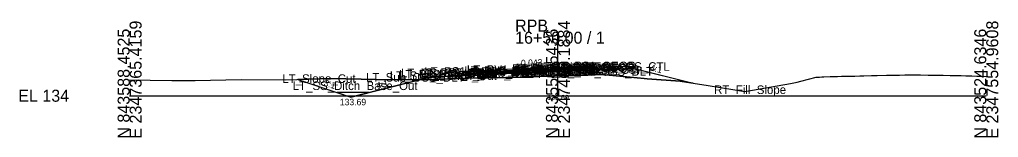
# Model space of a CAD drawing. Extents: x -76 to 2347760, y -10 to 844216.
# Drawn here: x -25.7 to 202.8, y 1490.3 to 1517.7 of the extents above; entities that cross this region are included whole.
import ezdxf

# ---------------------------------------------------------------- set-up
doc = ezdxf.new("R2010")
doc.units = 0
for name, color, linetype in [('Default', 7, 'Continuous'), ('Exist Cross Section Cell', 7, 'Continuous'), ('Exist XS Center Line Elevation Label', 7, 'Continuous'), ('Exist XS Ground Line', 7, 'Continuous'), ('Prop CMT Pvmt Course 1', 7, 'Continuous'), ('Prop CMT Pvmt Course 2', 7, 'Continuous'), ('Prop CMT Pvmt Course 3', 7, 'Continuous'), ('Prop CMT Pvmt Surface', 7, 'Continuous'), ('Prop CMT Pvmt Surface Shoulder', 7, 'Continuous'), ('Prop CMT Shld Paved Course 1', 7, 'Continuous'), ('Prop CMT Shld Paved Course 2', 7, 'Continuous'), ('Prop CMT Shld Paved Course 3', 7, 'Continuous'), ('Prop CMT Slope Grass', 7, 'Continuous'), ('Prop CMT Subgrade Earthwork', 7, 'Continuous'), ('Prop Road Sect_ Recs - UUC (Outline)', 7, 'Continuous'), ('Prop XS Ditch Standard Text', 7, 'Continuous'), ('Prop XS Earthwork Shape', 7, 'Continuous'), ('Prop XS SE Text', 7, 'Continuous'), ('Prop XS Side Slope Text', 7, 'Continuous'), ('Scratch_Level_0', 7, 'Continuous')]:
    doc.layers.add(name, color=color, linetype=linetype)

msp = doc.modelspace()

# ---------------------------------------------------------------- linework, layer by layer
at = {"layer": 'Exist Cross Section Cell'}
for p, q in [((100, 1500), (100, 1514.91)), ((0, 1500), (100, 1500)), ((100, 1500), (200, 1500))]:
    msp.add_line(p, q, dxfattribs=at)
at = {"layer": 'Exist XS Ground Line'}
msp.add_lwpolyline([(0, 1503.69), (4.77, 1503.59), (9.86, 1503.56), (15.32, 1503.51), (26.08, 1503.74), (36.43, 1503.71), (41.68, 1503.88), (46.98, 1504.01), (57.59, 1503.81), (68.08, 1503.69), (73.49, 1503.88), (78.63, 1504.12), (88.76, 1504.26), (89.4, 1504.28), (100, 1504.6), (105.31, 1504.73), (110.29, 1504.97), (120.1, 1503.98), (120.84, 1503.9), (128.55, 1503.38), (135.08, 1502.36), (140.86, 1501.43), (143.65, 1500.98), (154.26, 1502.88), (155.87, 1503.17), (156.69, 1503.39), (160.29, 1504.3), (161.06, 1504.31), (161.61, 1504.38), (162.08, 1504.4), (163.53, 1504.44), (165.29, 1504.49), (166.19, 1504.52), (167.97, 1504.57), (168.81, 1504.58), (169.33, 1504.59), (170.48, 1504.61), (171.38, 1504.64), (173.23, 1504.68), (174.08, 1504.7), (174.52, 1504.71), (176.73, 1504.76), (178.54, 1504.8), (179.35, 1504.81), (179.75, 1504.82), (180.99, 1504.85), (182.04, 1504.87), (182.6, 1504.87), (183.24, 1504.86), (184.61, 1504.85), (186.46, 1504.82), (187.25, 1504.81), (187.64, 1504.81), (188.86, 1504.79), (189.91, 1504.77), (191.59, 1504.73), (192.53, 1504.71), (194.17, 1504.68), (195.24, 1504.66), (196.65, 1504.6), (197.81, 1504.57), (198.42, 1504.54), (200, 1504.49)], dxfattribs=at)
at = {"layer": 'Prop CMT Pvmt Course 1'}
for p, q in [((100, 1506.59), (88, 1506.07)), ((88, 1505.82), (100, 1506.34)), ((88, 1506.07), (88, 1505.82)), ((100, 1506.59), (104, 1506.76)), ((100, 1506.34), (100, 1506.59)), ((100, 1506.34), (100, 1506.59)), ((104, 1506.51), (100, 1506.34)), ((100, 1506.34), (100, 1506.46)), ((100, 1506.46), (100, 1506.46)), ((100, 1506.46), (100, 1506.34)), ((100, 1506.34), (100, 1506.46)), ((100, 1506.46), (100, 1506.46)), ((100, 1506.46), (100, 1506.34)), ((100, 1506.34), (100, 1506.34)), ((100, 1506.34), (100, 1506.34)), ((104, 1506.76), (104, 1506.51))]:
    msp.add_line(p, q, dxfattribs=at)
at = {"layer": 'Prop CMT Pvmt Course 2'}
for p, q in [((100, 1506.34), (88, 1505.82)), ((100, 1506.34), (104, 1506.51)), ((100, 1506.01), (100, 1506.34)), ((100, 1506.01), (100, 1506.34)), ((104, 1506.18), (100, 1506.01)), ((104, 1506.51), (104, 1506.18)), ((88, 1505.49), (100, 1506.01)), ((88, 1505.82), (88, 1505.49))]:
    msp.add_line(p, q, dxfattribs=at)
at = {"layer": 'Prop CMT Pvmt Course 3'}
for p, q in [((100, 1506.01), (104, 1506.18)), ((104, 1506.18), (104, 1505.85)), ((100, 1506.01), (88, 1505.49)), ((88, 1505.15), (100, 1505.67)), ((88, 1505.49), (88, 1505.15)), ((100, 1505.67), (100, 1506.01)), ((100, 1505.67), (100, 1506.01)), ((104, 1505.85), (100, 1505.67))]:
    msp.add_line(p, q, dxfattribs=at)
at = {"layer": 'Prop CMT Pvmt Surface'}
for q in [(88, 1506.07), (104, 1506.76)]:
    msp.add_line((100, 1506.59), q, dxfattribs=at)
at = {"layer": 'Prop CMT Pvmt Surface Shoulder'}
for p, q in [((88, 1506.07), (78, 1505.64)), ((104, 1506.76), (108, 1506.94))]:
    msp.add_line(p, q, dxfattribs=at)
at = {"layer": 'Prop CMT Shld Paved Course 1'}
for p, q in [((88, 1506.07), (78, 1505.64)), ((88, 1505.82), (88, 1506.07)), ((104, 1506.76), (108, 1506.94)), ((104, 1506.51), (104, 1506.76)), ((108.24, 1506.7), (104, 1506.51)), ((108, 1506.94), (108.24, 1506.7)), ((77.74, 1505.38), (88, 1505.82)), ((78, 1505.64), (77.74, 1505.38))]:
    msp.add_line(p, q, dxfattribs=at)
at = {"layer": 'Prop CMT Shld Paved Course 2'}
for p, q in [((104, 1506.51), (108.24, 1506.7)), ((104, 1506.18), (104, 1506.51)), ((108.56, 1506.38), (104, 1506.18)), ((108.24, 1506.7), (108.56, 1506.38)), ((77.39, 1505.03), (88, 1505.49)), ((77.74, 1505.38), (77.39, 1505.03)), ((88, 1505.82), (77.74, 1505.38)), ((88, 1505.49), (88, 1505.82))]:
    msp.add_line(p, q, dxfattribs=at)
at = {"layer": 'Prop CMT Shld Paved Course 3'}
for p, q in [((104, 1506.18), (108.56, 1506.38)), ((104, 1505.85), (104, 1506.18)), ((109.38, 1506.08), (104, 1505.85)), ((108.56, 1506.38), (109.06, 1506.4)), ((109.06, 1506.4), (109.38, 1506.08)), ((76.54, 1504.66), (88, 1505.15)), ((76.89, 1505.01), (76.54, 1504.66)), ((77.39, 1505.03), (76.89, 1505.01)), ((88, 1505.49), (77.39, 1505.03)), ((88, 1505.15), (88, 1505.49))]:
    msp.add_line(p, q, dxfattribs=at)
at = {"layer": 'Prop CMT Slope Grass'}
for p, q in [((108, 1506.94), (116, 1506.8)), ((108, 1506.94), (116, 1506.8)), ((116, 1506.8), (131.6, 1502.9)), ((39.28, 1503.8), (51.63, 1499.69)), ((74.24, 1505.34), (51.63, 1499.69)), ((78, 1505.64), (74.24, 1505.34))]:
    msp.add_line(p, q, dxfattribs=at)
at = {"layer": 'Prop CMT Subgrade Earthwork'}
for p, q in [((104, 1505.85), (117.49, 1506.43)), ((76.54, 1504.66), (70.48, 1504.4)), ((88, 1505.15), (76.54, 1504.66)), ((100, 1505.67), (88, 1505.15)), ((100, 1505.67), (104, 1505.85))]:
    msp.add_line(p, q, dxfattribs=at)
at = {"layer": 'Prop Road Sect_ Recs - UUC (Outline)'}
msp.add_lwpolyline([(48.49, 1500.73), (51.63, 1499.69), (55.83, 1500.73)], close=True, dxfattribs=at)
at = {"layer": 'Prop XS Earthwork Shape'}
for points in [[(100, 1505.67), (104, 1505.85), (117.49, 1506.43), (131.6, 1502.9), (128.55, 1503.38), (120.84, 1503.9), (120.1, 1503.98), (110.29, 1504.97), (105.31, 1504.73), (100, 1504.6), (89.4, 1504.28), (88.76, 1504.26), (78.63, 1504.12), (73.49, 1503.88), (68.08, 1503.69), (67.68, 1503.7), (70.48, 1504.4), (76.54, 1504.66), (88, 1505.15)], [(39.28, 1503.8), (51.63, 1499.69), (67.68, 1503.7), (57.59, 1503.81), (46.98, 1504.01), (41.68, 1503.88)]]:
    msp.add_lwpolyline(points, close=True, dxfattribs=at)

# ---------------------------------------------------------------- texts
at = {"layer": 'Default'}
msp.add_text('-', height=0.0001, dxfattribs=at).set_placement((0, 1500))
at = {"layer": 'Exist Cross Section Cell'}
for s, p in [('RPB', (90, 1514.91)), ('16+50.00 / 1', (90, 1512.11)), ('EL 134', (-26, 1498.6))]:
    msp.add_text(s, height=2.8, dxfattribs=at).set_placement(p)
for s, p in [('N 843588.4525', (0, 1490)), ('E 2347365.4159', (2.8, 1490)), ('N 843556.5436', (100, 1490)), ('E 2347460.1884', (102.8, 1490)), ('N 843524.6346', (200, 1490)), ('E 2347554.9608', (202.8, 1490))]:
    msp.add_text(s, height=2.8, rotation=90, dxfattribs=at).set_placement(p)
at = {"layer": 'Exist XS Center Line Elevation Label'}
msp.add_text('138.60', height=1.2, dxfattribs=at).set_placement((97.48, 1499))
at = {"layer": 'Prop XS Ditch Standard Text'}
msp.add_text('133.69', height=1.5, dxfattribs=at).set_placement((49.08, 1497.78))
at = {"layer": 'Prop XS SE Text'}
msp.add_text('0.043', height=1.5, rotation=2.4746, dxfattribs=at).set_placement((91.4, 1506.84))
at = {"layer": 'Prop XS Side Slope Text'}
for s, rotation, p in [('4:1', 345.5351, (121.42, 1505.92)), ('3:1', 341.6601, (45.2, 1502.4)), ('4:1', 14.0362, (57.82, 1501.6))]:
    msp.add_text(s, height=1.5, rotation=rotation, dxfattribs=at).set_placement(p)
at = {"layer": 'Scratch_Level_0'}
for s, p in [('LT_PS3_Shelf_Out', (62.87, 1504.01)), ('LT_GS_OS_CTL', (63.37, 1504.32)), ('LT_PS3_OEOP', (67.63, 1504.03)), ('LT_PS2_OEOP', (67.97, 1504.38)), ('LT_PS1_OEOP', (68.8, 1504.64)), ('LT_Sub_OEOT', (78.08, 1504.15)), ('LT_PV2_OEOT', (78.17, 1504.82)), ('LT_PV3_OEOT', (78.17, 1504.49)), ('LT_PV1_OEOT', (78.74, 1505.07)), ('RT_Sub_OEEOP', (89.17, 1504.67)), ('LT_Sub_OEEOP', (89.21, 1504.67)), ('RT_PV2_OEEOP', (89.26, 1505.34)), ('RT_PV3_OEEOP', (89.26, 1505.01)), ('LT_PV2_OEEOP', (89.31, 1505.34)), ('LT_PV3_OEEOP', (89.31, 1505.01)), ('RT_PV1_OEEOP', (89.83, 1505.46)), ('LT_PV1_OEEOP', (89.87, 1505.46)), ('RT_PV2_IEEOP', (89.91, 1505.34)), ('LT_PV2_IEEOP', (89.95, 1505.34)), ('RT_PV1_IEEOP', (90.47, 1505.46)), ('LT_PV1_IEEOP', (90.52, 1505.46)), ('RT_Sub_Trench_Out', (93.54, 1505.08)), ('PV2_PGL', (93.91, 1505.34)), ('RT_Sub_OEOT', (94.03, 1504.85)), ('RT_PV2_OEOT', (94.13, 1505.51)), ('RT_PV3_OEOT', (94.13, 1505.18)), ('PV1_PGL', (94.47, 1505.59)), ('RT_PV1_OEOT', (94.69, 1505.76)), ('RT_PS3_Shelf_Out', (95, 1505.4)), ('RT_PS2_OEOP', (98.43, 1505.7)), ('RT_PS3_OEOP', (98.75, 1505.38)), ('RT_Sub_OSS_DLT', (98.75, 1504.65)), ('RT_PS1_OEOP', (98.76, 1505.94)), ('RT_GS_OS_CTL', (105.32, 1505.8)), ('LT_Slope_Cut', (35.65, 1502.99)), ('LT_Sub_OSS_DLT', (55.17, 1503.28)), ('LT_Sub_Trench_Out', (60.75, 1503.66)), ('LT_SS_Ditch_Base_Out', (38.08, 1501.32)), ('RT_Fill_Slope', (136.47, 1500.4))]:
    msp.add_text(s, height=2, dxfattribs=at).set_placement(p)

doc.saveas('drawing.dxf')
